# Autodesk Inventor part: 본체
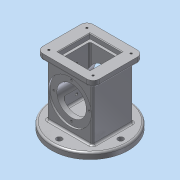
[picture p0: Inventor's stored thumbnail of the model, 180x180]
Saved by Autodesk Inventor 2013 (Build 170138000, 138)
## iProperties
Created: 2018-10
Part Number: 본체
Material: 알루미늄 6061
Document SubType Name: Modeling
Designer: Gpr
Density: 2.71 g/cm^3
Mass: 988.235 g
Surface Area: 743.898 cm^2
Volume: 364.662 cm^3
Author: Gpr
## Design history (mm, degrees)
sketch "스케치1"
  geometry: L1 (37, -33)-(-37, -33); L2 (-37, -33)-(-37, 33); L3 (-37, 33)-(37, 33); L4 (37, 33)-(37, -33); L5 (37, -33)-(-37, 33); L6 (-37, -33)-(37, 33); 1 further point
  constraints: 12 end point, 2 midpoint, 2 parallel, 1 horizontal, 1 perpendicular
  dimensions: "d0" = 74 distance of L2.end L3.end; "d2" = 66 distance of L3.end L1.start
extrude "돌출1" new body sketch "스케치1" stored distance "d3" = 108; taper "d4" = 0 deg
sketch "스케치2"
  geometry: L1 (-37, -33)-(37, -33) reference; L2 (37, -33)-(37, 33) reference; L3 (37, 33)-(-37, 33) reference; L4 (-37, 33)-(-37, -33) reference; L5 (46, -41)-(-46, -41); L6 (-46, -41)-(-46, 41); L7 (-46, 41)-(46, 41); L8 (46, 41)-(46, -41); L9 (46, -41)-(-46, 41); L10 (-46, -41)-(46, 41); 3 further points
  constraints: 12 end point, 3 midpoint, 2 parallel, 1 coincident, 1 horizontal, 1 perpendicular
  dimensions: "d5" = 92 distance of L6.end L7.end; "d7" = 82 distance of L7.end L5.start
extrude "돌출2" join sketch "스케치2" distance "d8" = 10; taper "d9" = 0 deg
sketch "스케치3"
  geometry: L1 (26, -26)-(-26, -26); L2 (-26, -26)-(-26, 26); L3 (-26, 26)-(26, 26); L4 (26, 26)-(26, -26); L5 (26, -26)-(-26, 26); L6 (-26, -26)-(26, 26); 1 further point
  constraints: 12 end point, 2 midpoint, 2 parallel, 1 horizontal, 1 perpendicular
  dimensions: "d10" = 52 distance of L2.end L3.end; "d12" = 52 distance of L3.end L1.start
extrude "돌출3" cut sketch "스케치3" distance "d13" = 8; taper "d14" = 0 deg
sketch "스케치4"
  geometry: L1 (22, -22)-(-22, -22); L2 (-22, -22)-(-22, 22); L3 (-22, 22)-(22, 22); L4 (22, 22)-(22, -22); L5 (22, -22)-(-22, 22); L6 (-22, -22)-(22, 22); 1 further point
  constraints: 12 end point, 2 midpoint, 2 parallel, 1 horizontal, 1 perpendicular
  dimensions: "d15" = 44 distance of L2.end L3.end; "d17" = 44 distance of L3.end L1.start
extrude "돌출4" cut sketch "스케치4" distance "d18" = 74; taper "d19" = 0 deg
fillet "모깎기1" dims "d20" = 3
fillet "모깎기2" dims "d21" = 3
chamfer "모따기1" distance "d22" = 1; stored, may be unused: second distance "d23" = 2, angle "d24" = 45 deg
sketch "스케치5"
  geometry: L1 (0, 0)-(74, 0) reference; C1 r 35 at (37, -54); 2 further points
  constraints: 1 centre point, 1 midpoint, 1 vertical alignment
  dimensions: "d25" = 54 distance from line of L1 C1.centre; "d26" = 70 diameter of C1
extrude "돌출5" cut sketch "스케치5" distance "d27" = 3; taper "d28" = 0 deg
sketch "스케치6"
  geometry: 1 further point
hole "구멍1" sketch "스케치6" at (37, 54) diameter "d29" = 48; stored, may be unused: countersink angle "d33" = 90 deg, drill point angle "d35" = 118 deg; dims "d30" = 6, "d31" = 70, "d32" = 3, "d34" = 8
sketch "스케치7"
  geometry: C1 r 24 at (0, 0) reference; 1 further point
  constraints: 1 vertical alignment
  dimensions: "d36" = 29 distance of C1.centre point (0, -29)
hole "구멍2" sketch "스케치7" at (0, -29) diameter "d37" = 3.242; stored, may be unused: countersink angle "d41" = 90 deg, drill point angle "d43" = 118 deg; dims "d38" = 4, "d39" = 70, "d40" = 3, "d42" = 6
sketch "스케치8"
  geometry: L1 (-37, -33)-(37, -33) reference; L2 (37, -33)-(37, 33) reference; L3 (37, 33)-(-37, 33) reference; L4 (-37, 33)-(-37, -33) reference; C1 r 62.5 at (0, 0); 1 further point
  constraints: 1 centre point, 1 coincident
  dimensions: "d47" = 125 diameter of C1
extrude "돌출6" join sketch "스케치8" distance "d49" = 10; taper "d50" = 0 deg
sketch "스케치9"
  geometry: C1 r 62.5 at (0, 0) reference; 1 further point
  constraints: 1 vertical alignment
  dimensions: "d51" = 50 distance of C1.centre point (0, 50)
hole "구멍3" sketch "스케치9" at (0, 50) diameter "d52" = 9; stored, may be unused: countersink angle "d56" = 90 deg, drill point angle "d58" = 0 deg; dims "d53" = 4, "d54" = 70, "d55" = 3, "d57" = 6
fillet "모깎기3" dims "d62" = 3
sketch "스케치10"
  geometry: L1 (36, -31)-(-36, -31); L2 (-36, -31)-(-36, 31); L3 (-36, 31)-(36, 31); L4 (36, 31)-(36, -31); L5 (36, -31)-(-36, 31); L6 (-36, -31)-(36, 31); 5 further points
  constraints: 12 end point, 4 coincident, 2 midpoint, 2 parallel, 1 horizontal, 1 perpendicular
  dimensions: "d63" = 72 distance of L2.end L3.end; "d65" = 62 distance of L3.end L1.start
hole "구멍4" sketch "스케치10" at (-36, 31), (36, 31), (36, -31), (-36, -31) diameter "d66" = 3.242; stored, may be unused: countersink angle "d70" = 90 deg, drill point angle "d72" = 118 deg; dims "d67" = 4, "d68" = 70, "d69" = 3, "d71" = 6
fillet "모깎기4" dims "d73" = 10
fillet "모깎기5" dims "d74" = 3
sketch "스케치11"
  geometry: L1 (-10, -32.5)-(-10, 92.5) reference; 3 further points
  constraints: 2 horizontal alignment
  dimensions: "d75" = 43 distance of point (27, 30) point (70, 30); "d77" = 37 distance from line of L1 point (27, 30)
hole "구멍5" sketch "스케치11" diameter "d78" = 4.134; stored, may be unused: countersink angle "d82" = 90 deg, drill point angle "d84" = 0 deg; dims "d79" = 4, "d80" = 70, "d81" = 3, "d83" = 6
hole "구멍6" sketch "스케치11" diameter "d85" = 4.134; stored, may be unused: countersink angle "d89" = 90 deg, drill point angle "d91" = 0 deg; dims "d86" = 4, "d87" = 70, "d88" = 3, "d90" = 6
sketch "스케치12"
  geometry: L1 (0, 0)-(72, 0) reference; L2 (82, 0)-(82, 10) reference; 2 further points
  constraints: 1 other
  dimensions: "d92" = 4 distance from line of L1 point (36, 4); "d93" = 46 distance from line of point (36, 4) L2
feature "엠보싱1" sketch "스케치12" dims "d0" = 74, "d2" = 66, "d8" = 10, "d9" = 0, "d94" = 0.5, "d95" = 0
fillet "모깎기6" dims "d96" = 3
sketch "스케치13"
  geometry: C1 r 62.5 at (0, 0) reference; C2 r 28 at (0, 0)
  constraints: 1 centre point, 1 coincident
  dimensions: "d97" = 56 diameter of C2
extrude "돌출7" cut sketch "스케치13" distance "d99" = 18; taper "d100" = -10 deg
fillet "모깎기7" dims "d101" = 3
fillet "모깎기8" dims "d102" = 3
node "솔리드1"
pattern_circular "원형 패턴1" dims angle "d45" = 360 deg
mirror "대칭1"
pattern_circular "원형 패턴2" dims angle "d60" = 360 deg
